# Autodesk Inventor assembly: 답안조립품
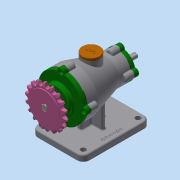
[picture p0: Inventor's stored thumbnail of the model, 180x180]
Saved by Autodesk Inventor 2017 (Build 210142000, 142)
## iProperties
Part Number: 답안조립품
Material: 일반
Document SubType Name: Assembly
Designer: 222
Author: 222
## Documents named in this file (14)
- C:\Users\222\Downloads\701206V1024\답안조립품.iam
- C:\Users\222\Downloads\701206V1024\본체.ipt
- C:\Users\222\Downloads\701206V1024\축.ipt
- C:\Users\222\Downloads\701206V1024\베어링 6203.ipt
- C:\Users\222\Downloads\701206V1024\키 4x4x14.ipt
- C:\Users\222\Downloads\701206V1024\개스킷 A.ipt
- C:\Users\222\Downloads\701206V1024\개스킷 B.ipt
- C:\Users\222\Downloads\701206V1024\앞커버.ipt
- C:\Users\222\Downloads\701206V1024\오일 실 17 30 8.ipt
- C:\Users\222\Downloads\701206V1024\뒤커버.ipt
- C:\Users\222\Downloads\701206V1024\베어링 6200.ipt
- C:\Users\222\Downloads\701206V1024\오일 실 10 20 7.ipt
- C:\Users\222\Downloads\701206V1024\스프로킷.ipt
- C:\Users\222\Downloads\701206V1024\마개.ipt
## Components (2 placed, 2 different names)
1. 개스킷 A:1
2. 개스킷 B:1
